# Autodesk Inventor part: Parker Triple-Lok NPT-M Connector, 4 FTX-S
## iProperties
Shininess: 20.0
Length Units: 11272
Angle Units: 11279
Time Units: 11290
Mass Units: 11286
Length Display Precision: 3
Angle Display Precision: 2
Created: 2001-09
Part Number: Parker Triple-Lok NPT-M Connector, 4 FTX-S
Material: Stainless Steel, Austenitic
Description: Parker Triple-Lok NPT-M Connector, 4 FTX-S
Document SubType Name: Modeling
Designer: jhagarty
Density: 0.0
Volumn: 0.0
Area: 0.0
PropertySet Name: Model Information
Control State: 0
Master: False
Checked Out: False
Last Check In By: Charles Bliss
Last Check In Date: 2003-09-27
Author: jhagarty
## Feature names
1. Extrusion1
2. Revolution3
3. Mirror2
4. Revolution1
5. Extrusion2
6. Hole3
7. Hole4
